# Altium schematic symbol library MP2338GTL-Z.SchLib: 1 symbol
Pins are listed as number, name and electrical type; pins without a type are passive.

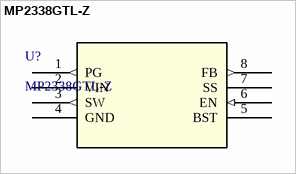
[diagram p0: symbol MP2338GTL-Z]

## MP2338GTL-Z
designator U?
High-Efficiency 28V 3A 450kHz Synchronous Step-Down Converter In SOT583 Package; Manufacturer_Name: Monolithic Power Systems
footprint SOT583_MP2338_MNP
pins: 1 PG (out), 2 VIN (power), 3 SW (out), 4 GND (power), 5 BST (power), 6 EN (in), 7 SS, 8 FB (out)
